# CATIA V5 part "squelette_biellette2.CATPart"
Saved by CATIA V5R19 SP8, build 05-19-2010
Part number: squelette_biellette2
Publications: "Droite.1", "Droite.2", "Plan.1"
Bounding box of the stored display mesh (mm): x 83 to 83, y 240.283 to 275.479, z 39.102 to 112.052
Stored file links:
  G:\EU_thinkMotion\CFAO_2010\MMS_groupe3\MMS_groupe3\A reprendre\amenand\amenand\squelette_biellette2.CATPart
  F:\thinkmotion CFAO v12.1\essuie_glace.CATProduct
  G:\EU_thinkMotion\CFAO_2010\MMS_groupe3\MMS_groupe3\A reprendre\amenand\amenand\squelette_biellette1.CATPart
  G:\EU_thinkMotion\CFAO_2010\MMS_groupe3\MMS_groupe3\A reprendre\amenand\amenand\squelette_bielle.CATPart
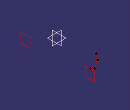
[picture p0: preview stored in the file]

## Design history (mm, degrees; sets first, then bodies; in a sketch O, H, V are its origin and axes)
Set1
  Point1: linked copy from another document
  Plane1: linked copy from another document
  Plane2: linked copy from another document
  Point2: linked copy from another document
Set2 "set géométrique.6"
  Point3: type OnPlane, Support Plane1, H 259.837, V 48.525, Direction (0, 1, 0)
  Point4: type OnPlane, Support Plane1, H 275.479, V 92.209, Direction (0, 1, 0)
  Line1: type PtPt, FirstPoint Point4, SecondPoint Point3
  Line2: type PtPt, FirstPoint Point1, SecondPoint Point3
  Line3: type PtPt, FirstPoint Point2, SecondPoint Point4
Body1 (main body)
